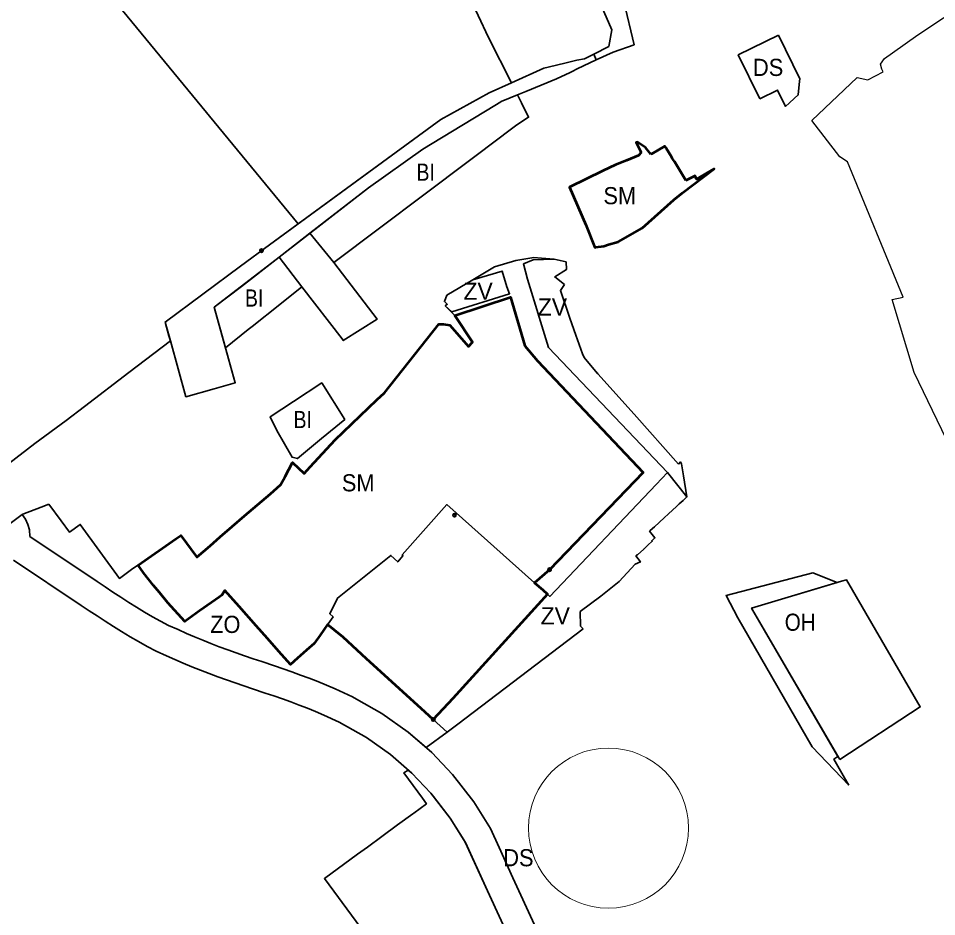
# Model space of a CAD drawing. Extents: x -650276 to -642489, y -1074311 to -1066658.
# Drawn here: x -648072 to -647429, y -1071706 to -1071077 of the extents above; entities that cross this region are included whole.
import ezdxf

# ---------------------------------------------------------------- set-up
doc = ezdxf.new("R2010")
doc.units = 0
doc.header["$LTSCALE"] = 4.8
doc.header["$PDMODE"] = 32
doc.header["$PDSIZE"] = 2.4
for name, color, linetype, lineweight in [('1', 7, 'Continuous', 35), ('10', 7, 'Continuous', 35), ('15', 7, 'Continuous', 35), ('18', 7, 'Continuous', 35), ('2', 7, 'Continuous', 35), ('24', 7, 'Continuous', 35), ('40', 7, 'Continuous', 35), ('42', 7, 'Continuous', 35), ('54', 7, 'Continuous', 35), ('60', 7, 'Continuous', 53), ('61', 7, 'Continuous', 25)]:
    doc.layers.add(name, color=color, linetype=linetype, lineweight=lineweight)
doc.layers.add('62', color=7, linetype='Continuous')

msp = doc.modelspace()

# ---------------------------------------------------------------- linework, layer by layer
at = {"layer": '1'}
msp.add_lwpolyline([(-648001.922, -1071067.83), (-647977.41, -1071049.74), (-647930.7, -1071017.18), (-647911.838, -1071002.919), (-647864.03, -1070969.3), (-647864.03, -1070969.3), (-647818.33, -1070942.91), (-647810.243, -1070939.825), (-647759.52, -1071055.67), (-647757.19, -1071059.66), (-647742.64, -1071090.72), (-647726.74, -1071122.48), (-647742.35, -1071129.43), (-647775.982, -1071148.001), (-647775.982, -1071148.001), (-647875.939, -1071221.104)], close=True, dxfattribs=at)
at = {"layer": '10'}
msp.add_lwpolyline([(-647497.04, -1071595.66), (-647440.67, -1071558.93), (-647492.3, -1071470), (-647495.85, -1071471.06), (-647558.654, -1071489.738)], close=True, dxfattribs=at)
at = {"layer": '15'}
for p, q in [((-647873.25, -1071265.17), (-647845.18, -1071301.54)), ((-647708.429, -1071316.821), (-647717.363, -1071306.29))]:
    msp.add_line(p, q, dxfattribs=at)
for points in [[(-647640.727, -1071095.819), (-647648.106, -1071065.551), (-647654.747, -1071047.095), (-647657.699, -1071038.232), (-647659.01, -1071032.66)], [(-647676.96, -1071039.014), (-647676.9, -1071039.03), (-647676.45, -1071039.22), (-647656.443, -1071085.369), (-647658.55, -1071097.02), (-647669.02, -1071102.33), (-647667.35, -1071106.38), (-647655.47, -1071100.98), (-647640.727, -1071095.819)], [(-647845.18, -1071301.54), (-647844.296, -1071302.757), (-647820.698, -1071287.83), (-647850.956, -1071248.208), (-647867.586, -1071227.694), (-647889.22, -1071244.48), (-647873.25, -1071265.17)], [(-647498.271, -1071593.544), (-647558.654, -1071489.738), (-647498.8, -1071471.94), (-647515.87, -1071465.25), (-647576.471, -1071481.091), (-647568.35, -1071496.656), (-647516.376, -1071586.89), (-647490.561, -1071613.609)], [(-647490.561, -1071613.609), (-647493.6, -1071608.5), (-647501.11, -1071595.45), (-647498.271, -1071593.544)]]:
    msp.add_lwpolyline(points, dxfattribs=at)
for points in [[(-647826.56, -1071195.86), (-647788.66, -1071168.8), (-647761.366, -1071152.304), (-647737.027, -1071137.593), (-647733.38, -1071135.37), (-647732.58, -1071135.04), (-647722.51, -1071130.93), (-647716.51, -1071128.48), (-647695.08, -1071119.72), (-647685.55, -1071115.14), (-647684.15, -1071114.47), (-647680.64, -1071112.77), (-647667.35, -1071106.38), (-647669.02, -1071102.33), (-647674.17, -1071104.97), (-647675.64, -1071105.71), (-647680.82, -1071106.54), (-647688.45, -1071108.38), (-647701.04, -1071111.41), (-647703.96, -1071112.11), (-647726.74, -1071122.48), (-647742.35, -1071129.43), (-647775.982, -1071148.001), (-647895.959, -1071235.746), (-647916.161, -1071250.628), (-647916.208, -1071250.662), (-647968.896, -1071289.779), (-647965.26, -1071302.86), (-647954.38, -1071342), (-647934.51, -1071336.37), (-647919.88, -1071332.23), (-647924.53, -1071315.55), (-647934.6, -1071279.45), (-647915.6, -1071264.95), (-647889.22, -1071244.48)], [(-647625.428, -1071403.267), (-647617.49, -1071394.901), (-647700.816, -1071307.512), (-647715.355, -1071259.885), (-647718.342, -1071248.972), (-647711.447, -1071246.332), (-647696.81, -1071245.79), (-647705.59, -1071245.08), (-647710.94, -1071244.65), (-647723.57, -1071246.66), (-647738.56, -1071251.13), (-647753.647, -1071260.178), (-647733.15, -1071254.081), (-647729.795, -1071265.066), (-647728.006, -1071269.975), (-647768.445, -1071282.6), (-647772.97, -1071278.43), (-647772.07, -1071279.33), (-647766.35, -1071285.11), (-647727.368, -1071272.362), (-647717.363, -1071306.29), (-647708.429, -1071316.821), (-647634.524, -1071394.901), (-647700.078, -1071462.96), (-647710.546, -1071472.023), (-647699.767, -1071481.617)]]:
    msp.add_lwpolyline(points, close=True, dxfattribs=at)
for p in [(-647766.557, -1071424.793), (-647700.078, -1071462.96)]:
    msp.add_point(p, dxfattribs=at)
at = {"layer": '18'}
for points in [[(-647629.09, -1071172.4), (-647632.93, -1071167.71), (-647638.46, -1071163.89), (-647639.32, -1071164.22), (-647635.93, -1071171.22)], [(-647612.695, -1071177.542), (-647613.91, -1071175.57), (-647614.732, -1071174.222), (-647618.446, -1071168.166), (-647618.469, -1071168.129), (-647618.77, -1071167.64), (-647619.264, -1071166.832), (-647619.34, -1071166.709), (-647628.39, -1071172.05), (-647629.09, -1071172.4)], [(-647635.93, -1071171.22), (-647637.87, -1071173.29), (-647646.09, -1071176.68), (-647653.85, -1071179.87), (-647662.634, -1071183.968)], [(-647604.576, -1071190.781), (-647604.888, -1071190.272), (-647612.695, -1071177.542)], [(-647662.634, -1071183.968), (-647686.01, -1071195.35), (-647686.01, -1071195.35)], [(-647674.6, -1071221.71), (-647668.226, -1071237.571), (-647667.77, -1071237.5), (-647661.99, -1071236.62), (-647658.78, -1071235.63), (-647651.93, -1071233.57), (-647635.17, -1071224.18), (-647613.09, -1071204.33), (-647607.02, -1071199.34), (-647584.92, -1071182.54), (-647597.164, -1071189.857), (-647598.215, -1071187.608), (-647604.576, -1071190.781)], [(-647686.01, -1071195.35), (-647686.01, -1071195.35), (-647674.6, -1071221.71)]]:
    msp.add_lwpolyline(points, dxfattribs=at)
msp.add_lwpolyline([(-647974.66, -1071450.62), (-647977.28, -1071452.43), (-647979.88, -1071454.22), (-647982.46, -1071456), (-647985.06, -1071457.79), (-647987.8, -1071459.68), (-647984.07, -1071465.1), (-647977.13, -1071474.05), (-647972.76, -1071479), (-647967.13, -1071486.01), (-647957.07, -1071497.13), (-647955.14, -1071499.23), (-647950.56, -1071495.85), (-647944.81, -1071491.78), (-647939.31, -1071487.88), (-647933.88, -1071484.04), (-647931.17, -1071482.12), (-647929.26, -1071480.77), (-647927.2, -1071477.54), (-647919.22, -1071486.5), (-647881.16, -1071529.25), (-647876.27, -1071524.96), (-647864.69, -1071514.65), (-647851.45, -1071495.96), (-647853.77, -1071493.78), (-647848.4, -1071482.78), (-647810.97, -1071452.92), (-647806.15, -1071457.48), (-647802.53, -1071453.19), (-647803.1, -1071452.66), (-647771.82, -1071417.42), (-647710.546, -1071472.023), (-647700.078, -1071462.96), (-647634.524, -1071394.901), (-647708.429, -1071316.821), (-647717.363, -1071306.29), (-647727.368, -1071272.362), (-647766.35, -1071285.11), (-647753.89, -1071303.94), (-647756.67, -1071306.77), (-647769.85, -1071291.91), (-647774.14, -1071291.34), (-647777.4, -1071291.32), (-647815.95, -1071339.71), (-647820.93, -1071344.25), (-647849.86, -1071372.18), (-647867.45, -1071390.95), (-647871.68, -1071395.59), (-647879.76, -1071387.96), (-647885.05, -1071397.88), (-647888.11, -1071403.61), (-647895.29, -1071409.81), (-647904.3, -1071417.58), (-647911.04, -1071423.39), (-647913.31, -1071425.35), (-647921.96, -1071432.81), (-647946.78, -1071454.23), (-647957.906, -1071439.06)], close=True, dxfattribs=at)
at = {"layer": '2'}
for points in [[(-648091.92, -1071399.07), (-648060.01, -1071374.69), (-648038.18, -1071358.51), (-648025.39, -1071348.76), (-647994.31, -1071325.03), (-647965.26, -1071302.86), (-647966.226, -1071299.385), (-647968.896, -1071289.779), (-647916.208, -1071250.662), (-647895.959, -1071235.746), (-647875.939, -1071221.104), (-648001.922, -1071067.83)], [(-647889.22, -1071244.48), (-647915.6, -1071264.95), (-647934.6, -1071279.45), (-647926.689, -1071307.809), (-647910.73, -1071295.08)], [(-647910.73, -1071295.08), (-647907.92, -1071292.84), (-647888.77, -1071277.56), (-647873.25, -1071265.17), (-647889.22, -1071244.48)]]:
    msp.add_lwpolyline(points, dxfattribs=at)
for points in [[(-647756.03, -1071176.76), (-647750.34, -1071172.5), (-647726.56, -1071154.68), (-647723.79, -1071152.61), (-647720.85, -1071150.41), (-647714.71, -1071146.51), (-647719.73, -1071136.48), (-647722.51, -1071130.93), (-647732.58, -1071135.04), (-647733.38, -1071135.37), (-647737.027, -1071137.593), (-647761.366, -1071152.304), (-647788.66, -1071168.8), (-647826.56, -1071195.86), (-647867.586, -1071227.694), (-647850.956, -1071248.208)], [(-647926.69, -1071307.81), (-647934.6, -1071279.45), (-647889.22, -1071244.48), (-647873.25, -1071265.17), (-647888.77, -1071277.56), (-647907.92, -1071292.84), (-647910.73, -1071295.08)], [(-647879.09, -1071345.3), (-647895.37, -1071355.96), (-647890.7, -1071365.52), (-647880.14, -1071384.32), (-647876.34, -1071385.2), (-647862.25, -1071373.55), (-647859.44, -1071371.23), (-647843.23, -1071357.82), (-647859.31, -1071332.34)]]:
    msp.add_lwpolyline(points, close=True, dxfattribs=at)
msp.add_point((-647901.523, -1071239.822), dxfattribs=at)
at = {"layer": '24'}
for points in [[(-647539.818, -1071089.2), (-647568.01, -1071102.98), (-647553.01, -1071133.68)], [(-647525.1, -1071121.25), (-647524.95, -1071119.68), (-647539.817, -1071089.199)], [(-647553.01, -1071133.68), (-647540.48, -1071127.55), (-647534.851, -1071139.015), (-647526.04, -1071130.94), (-647525.1, -1071121.25)], [(-648063.593, -1071439.723), (-648063.862, -1071435.078), (-648064.838, -1071431.28), (-648066.623, -1071427.592), (-648069.022, -1071424.443), (-648101.203, -1071448.31)], [(-647834.953, -1071553.406), (-647837.929, -1071551.872), (-647843.891, -1071549), (-647849.898, -1071546.282), (-647855.937, -1071543.707), (-647861.998, -1071541.254), (-647868.073, -1071538.911), (-647874.155, -1071536.658), (-647880.233, -1071534.48), (-647886.305, -1071532.36), (-647892.363, -1071530.282), (-647901.28, -1071527.249), (-647907.294, -1071525.204), (-647913.282, -1071523.152), (-647919.238, -1071521.081), (-647925.157, -1071518.976), (-647931.035, -1071516.824), (-647936.866, -1071514.613), (-647942.644, -1071512.329), (-647948.363, -1071509.96), (-647954.016, -1071507.496), (-647959.792, -1071504.833), (-647966.547, -1071501.883), (-647972.035, -1071499.009), (-647977.67, -1071495.885), (-647983.266, -1071492.628), (-647988.829, -1071489.259), (-647994.366, -1071485.79), (-647999.887, -1071482.241), (-648005.399, -1071478.627), (-648010.917, -1071474.963), (-648016.446, -1071471.268), (-648063.593, -1071439.723)], [(-648074.86, -1071456.248), (-648027.562, -1071487.894), (-648022.005, -1071491.607), (-648016.415, -1071495.321), (-648010.777, -1071499.017), (-648005.082, -1071502.678), (-647999.319, -1071506.287), (-647993.478, -1071509.826), (-647987.55, -1071513.275), (-647981.525, -1071516.615), (-647975.201, -1071519.929), (-647967.982, -1071523.081), (-647962.2, -1071525.746), (-647956.187, -1071528.368), (-647950.146, -1071530.869), (-647944.088, -1071533.263), (-647938.019, -1071535.566), (-647931.945, -1071537.788), (-647925.874, -1071539.949), (-647919.808, -1071542.058), (-647913.756, -1071544.132), (-647907.72, -1071546.185), (-647898.827, -1071549.208), (-647892.847, -1071551.26), (-647886.903, -1071553.336), (-647881.001, -1071555.45), (-647875.147, -1071557.619), (-647869.348, -1071559.856), (-647863.611, -1071562.177), (-647857.944, -1071564.594), (-647847.103, -1071569.497)], [(-647725.629, -1071678.373), (-647735.352, -1071657.117), (-647741.34, -1071644.028), (-647753.065, -1071625.201), (-647767.784, -1071606.225), (-647782.408, -1071590.847), (-647798.911, -1071576.526), (-647817.375, -1071563.458), (-647834.953, -1071553.406)], [(-647847.103, -1071569.497), (-647828.141, -1071580.34), (-647811.272, -1071592.28), (-647796.24, -1071605.324), (-647782.97, -1071619.278)], [(-647782.97, -1071619.278), (-647769.498, -1071636.647), (-647758.994, -1071653.513), (-647743.48, -1071687.426), (-647611.514, -1071974.086)], [(-647570.747, -1071972.644), (-647538.922, -1071950.099), (-647551.962, -1071958.049), (-647573.283, -1071969.627), (-647575.415, -1071967.709), (-647577.881, -1071965.979), (-647581.036, -1071964.346), (-647584.363, -1071963.196), (-647588.064, -1071962.51), (-647591.518, -1071962.387), (-647594.731, -1071962.714), (-647725.614, -1071678.405), (-647726.774, -1071675.885), (-647725.629, -1071678.373)]]:
    msp.add_lwpolyline(points, dxfattribs=at)
at = {"layer": '40'}
msp.add_line((-647617.49, -1071394.901), (-647603.9, -1071412.1), dxfattribs=at)
for points in [[(-647696.81, -1071245.79), (-647711.447, -1071246.332), (-647718.342, -1071248.972), (-647715.355, -1071259.885), (-647700.816, -1071307.512), (-647617.49, -1071394.901)], [(-647689.61, -1071263.51), (-647696.35, -1071258.14), (-647688.17, -1071253.06), (-647688.46, -1071247.65), (-647696.81, -1071245.79)], [(-647728.006, -1071269.975), (-647729.795, -1071265.066), (-647733.15, -1071254.081), (-647753.647, -1071260.178), (-647771.76, -1071271.04)], [(-647666.78, -1071325.52), (-647675.85, -1071314.62), (-647677, -1071312.01), (-647681.53, -1071299.02), (-647685.74, -1071286.93), (-647692.45, -1071267.67), (-647689.61, -1071263.51)], [(-647771.76, -1071271.04), (-647773.6, -1071275.43), (-647771.59, -1071277.36), (-647772.97, -1071278.43), (-647768.445, -1071282.6), (-647728.006, -1071269.975)], [(-647609.85, -1071389.21), (-647640.92, -1071354.21), (-647666.21, -1071325.89), (-647666.629, -1071325.351), (-647666.78, -1071325.52)], [(-647603.9, -1071412.1), (-647606.39, -1071397.21), (-647607.77, -1071388.91), (-647608.31, -1071387.63), (-647609.85, -1071389.21)], [(-647617.49, -1071394.901), (-647625.428, -1071403.267), (-647699.767, -1071481.617), (-647701.415, -1071480.15)], [(-647676.51, -1071504.34), (-647678.3, -1071502.55), (-647678.56, -1071492.25), (-647664.16, -1071481.45), (-647651.2, -1071471.24), (-647640.04, -1071458.97), (-647636.48, -1071457.52), (-647639.64, -1071453.33), (-647639.11, -1071452.78), (-647638.4, -1071452.55), (-647634.04, -1071448.58), (-647634.12, -1071448.49), (-647631.16, -1071445.79), (-647628.21, -1071443.09), (-647628.55, -1071442.72), (-647626.34, -1071440.73), (-647630.04, -1071435.97), (-647629.6, -1071435.56), (-647626.65, -1071432.87), (-647619.75, -1071426.57), (-647616.75, -1071423.83), (-647611.12, -1071418.69), (-647609.25, -1071416.99), (-647606.48, -1071414.46), (-647603.9, -1071412.1), (-647617.49, -1071394.901)], [(-647701.415, -1071480.15), (-647708.18, -1071487.57), (-647767.575, -1071553.083), (-647781.31, -1071567.79), (-647771.717, -1071576.551)], [(-647771.717, -1071576.551), (-647764.23, -1071571.01), (-647676.51, -1071504.34)]]:
    msp.add_lwpolyline(points, dxfattribs=at)
at = {"layer": '42'}
for p, q in [((-647984.07, -1071465.1), (-647987.8, -1071459.68)), ((-647849.898, -1071546.282), (-647843.891, -1071549))]:
    msp.add_line(p, q, dxfattribs=at)
for points in [[(-648050.25, -1071417.19), (-648055.717, -1071419.253), (-648068.56, -1071424.1), (-648069.022, -1071424.443)], [(-647987.8, -1071459.68), (-647988.713, -1071460.33), (-647992.408, -1071462.858), (-648000.91, -1071469.01), (-648028.31, -1071431.32), (-648035.87, -1071436.62), (-648041.726, -1071428.707), (-648050.25, -1071417.19)], [(-648069.022, -1071424.443), (-648066.623, -1071427.592), (-648064.838, -1071431.28), (-648063.862, -1071435.078), (-648063.593, -1071439.723), (-648016.446, -1071471.268), (-648010.917, -1071474.963), (-648005.399, -1071478.627), (-647999.887, -1071482.241), (-647994.366, -1071485.79)], [(-647944.81, -1071491.78), (-647950.56, -1071495.85), (-647955.14, -1071499.23), (-647957.07, -1071497.13), (-647967.13, -1071486.01), (-647972.76, -1071479), (-647977.13, -1071474.05)], [(-647927.2, -1071477.54), (-647927.2, -1071477.54), (-647929.26, -1071480.77), (-647931.17, -1071482.12), (-647933.88, -1071484.04), (-647939.31, -1071487.88), (-647944.81, -1071491.78)], [(-647855.23, -1071501.297), (-647864.69, -1071514.65), (-647876.27, -1071524.96), (-647881.16, -1071529.25), (-647919.22, -1071486.5), (-647927.2, -1071477.54)], [(-647994.366, -1071485.79), (-647988.829, -1071489.259), (-647983.266, -1071492.628)], [(-647983.266, -1071492.628), (-647977.67, -1071495.885), (-647972.035, -1071499.009), (-647966.547, -1071501.883), (-647959.792, -1071504.833)], [(-647828.024, -1071525.256), (-647844.4, -1071510.2), (-647850.55, -1071505.14), (-647855.23, -1071501.297)], [(-647959.792, -1071504.833), (-647954.016, -1071507.496), (-647948.363, -1071509.96)], [(-647948.363, -1071509.96), (-647942.644, -1071512.329), (-647936.866, -1071514.613)], [(-647936.866, -1071514.613), (-647931.035, -1071516.824), (-647925.157, -1071518.976), (-647919.238, -1071521.081), (-647913.282, -1071523.152)], [(-647781.31, -1071567.79), (-647789.73, -1071560.1), (-647844.4, -1071510.2), (-647828.024, -1071525.256)], [(-647913.282, -1071523.152), (-647907.294, -1071525.204), (-647901.28, -1071527.249)], [(-647901.28, -1071527.249), (-647892.363, -1071530.282), (-647886.305, -1071532.36), (-647880.233, -1071534.48), (-647874.155, -1071536.658), (-647868.073, -1071538.911), (-647861.998, -1071541.254), (-647855.937, -1071543.707), (-647849.898, -1071546.282)], [(-647843.891, -1071549), (-647837.929, -1071551.872), (-647834.953, -1071553.406)], [(-647834.953, -1071553.406), (-647817.375, -1071563.458), (-647798.911, -1071576.526), (-647786.379, -1071587.401), (-647771.717, -1071576.551), (-647781.31, -1071567.79)], [(-647727.85, -1071854.86), (-647857.52, -1071678.92), (-647834.345, -1071661.969), (-647827.42, -1071656.89), (-647817.33, -1071649.51), (-647806.35, -1071641.47), (-647795.76, -1071633.72), (-647794.98, -1071633.15), (-647786.1, -1071626.65), (-647788.942, -1071622.735), (-647801.84, -1071604.97), (-647798.8, -1071603.102), (-647796.24, -1071605.324), (-647782.97, -1071619.278), (-647781.134, -1071621.645), (-647769.498, -1071636.647), (-647758.889, -1071653.742), (-647743.48, -1071687.426), (-647611.514, -1071974.086)]]:
    msp.add_lwpolyline(points, dxfattribs=at)
msp.add_point((-647781.31, -1071567.79), dxfattribs=at)
at = {"layer": '54', "lineweight": 13}
msp.add_circle((-647658.811, -1071643.674), 55.982, dxfattribs=at)
at = {"layer": '60'}
for points in [[(-647629.09, -1071172.4), (-647632.93, -1071167.71), (-647638.46, -1071163.89), (-647639.32, -1071164.22), (-647635.93, -1071171.22)], [(-647612.695, -1071177.542), (-647613.91, -1071175.57), (-647614.732, -1071174.222), (-647618.446, -1071168.166), (-647618.469, -1071168.129), (-647618.77, -1071167.64), (-647619.264, -1071166.832), (-647619.34, -1071166.709), (-647628.39, -1071172.05), (-647629.09, -1071172.4)], [(-647635.93, -1071171.22), (-647637.87, -1071173.29), (-647646.09, -1071176.68), (-647653.85, -1071179.87), (-647662.634, -1071183.968)], [(-647604.576, -1071190.781), (-647604.888, -1071190.272), (-647612.695, -1071177.542)], [(-647662.634, -1071183.968), (-647686.01, -1071195.35), (-647686.01, -1071195.35)], [(-647674.6, -1071221.71), (-647668.226, -1071237.571), (-647667.77, -1071237.5), (-647661.99, -1071236.62), (-647658.78, -1071235.63), (-647651.93, -1071233.57), (-647635.17, -1071224.18), (-647613.09, -1071204.33), (-647607.02, -1071199.34), (-647584.92, -1071182.54), (-647597.164, -1071189.857), (-647598.215, -1071187.608), (-647604.576, -1071190.781)], [(-647686.01, -1071195.35), (-647686.01, -1071195.35), (-647674.6, -1071221.71)]]:
    msp.add_lwpolyline(points, dxfattribs=at)
msp.add_lwpolyline([(-647777.4, -1071291.32), (-647777.4, -1071291.32), (-647774.14, -1071291.34), (-647769.85, -1071291.91), (-647756.67, -1071306.77), (-647753.89, -1071303.94), (-647766.35, -1071285.11), (-647727.368, -1071272.362), (-647717.363, -1071306.29), (-647708.429, -1071316.821), (-647634.524, -1071394.901), (-647700.078, -1071462.96), (-647710.546, -1071472.023), (-647704.78, -1071477.1), (-647701.415, -1071480.15), (-647708.18, -1071487.57), (-647767.575, -1071553.083), (-647781.31, -1071567.79), (-647789.73, -1071560.1), (-647828.024, -1071525.256), (-647844.4, -1071510.2), (-647850.55, -1071505.14), (-647855.23, -1071501.297), (-647860.576, -1071508.843), (-647864.69, -1071514.65), (-647869.922, -1071519.269), (-647876.29, -1071524.89), (-647881.16, -1071529.25), (-647883.31, -1071526.83), (-647889.29, -1071520.11), (-647897.27, -1071511.15), (-647905.25, -1071502.19), (-647917.23, -1071488.75), (-647927.2, -1071477.54), (-647929.26, -1071480.77), (-647931.17, -1071482.12), (-647936.59, -1071485.96), (-647944.81, -1071491.78), (-647955.14, -1071499.23), (-647967.13, -1071486.01), (-647972.76, -1071479), (-647977.13, -1071474.05), (-647984.07, -1071465.1), (-647987.8, -1071459.68), (-647961.4, -1071441.47), (-647957.906, -1071439.06), (-647946.78, -1071454.23), (-647937.43, -1071446.16), (-647930.38, -1071440.08), (-647921.96, -1071432.81), (-647913.31, -1071425.35), (-647904.3, -1071417.58), (-647895.29, -1071409.81), (-647888.11, -1071403.61), (-647885.05, -1071397.88), (-647879.76, -1071387.96), (-647871.68, -1071395.59), (-647867.45, -1071390.95), (-647849.86, -1071372.18), (-647820.93, -1071344.25), (-647815.474, -1071339.22)], close=True, dxfattribs=at)
at = {"layer": '61'}
msp.add_lwpolyline([(-647415.97, -1071385.01), (-647445, -1071324.99), (-647460.28, -1071274.02), (-647452.69, -1071272.32), (-647491.56, -1071177.65), (-647497.03, -1071174.18), (-647516.65, -1071148.87), (-647484.84, -1071118.8), (-647477.3, -1071120.38), (-647466.6, -1071114.88), (-647467.47, -1071112.93), (-647468.47, -1071109.42), (-647465.83, -1071105.54), (-647460.06, -1071101.57), (-647442.36, -1071088.82), (-647406.52, -1071065.05)], dxfattribs=at)

# ---------------------------------------------------------------- texts
at = {"layer": '62'}
for s, width, p in [('DS', 0.95, (-647557.693, -1071117.661)), ('BI', 0.85, (-647793.1, -1071190.942)), ('SM', 0.95, (-647662.328, -1071207.374)), ('BI', 0.85, (-647913.1, -1071278.942)), ('BI', 0.85, (-647879.1, -1071363.942)), ('SM', 0.95, (-647845.307, -1071408.18)), ('ZO', 0.95, (-647937.423, -1071507.188)), ('OH', 0.9, (-647535.508, -1071505.684)), ('DS', 0.95, (-647732.378, -1071670.379))]:
    msp.add_text(s, height=12, dxfattribs=dict(at, width=width)).set_placement(p)
for p in [(-647760.241, -1071274.214), (-647708.241, -1071285.214), (-647706.241, -1071501.214)]:
    msp.add_text('ZV', height=12, dxfattribs=at).set_placement(p)

doc.saveas('drawing.dxf')
